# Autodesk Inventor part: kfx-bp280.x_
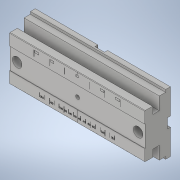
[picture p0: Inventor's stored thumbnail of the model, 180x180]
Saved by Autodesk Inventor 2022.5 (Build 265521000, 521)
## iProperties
Created: 2021-10
Part Number: kfx-bp280.x_
Material: 一般
Document SubType Name: Modeling
Designer: ImaoCorp
Density: 1 g/cm^3
Appearance: 既定
Sending System: SOLIDWORKS 2019-2019304
MC: AMD64
MC_MODEL: Intel64 Family 6 Model 60 Stepping 3, GenuineIntel
OS: Windows_NT
FRU: Parasolid Version 31.0, build 290,  9- 1-2019
FORMAT: text
GUISE: transmit
KEY: kfx-bp280
FILE: kfx-bp280.x_t
DATE: Thu Oct 14 10:00:54 2021
Author: ImaoCorp
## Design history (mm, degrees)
feature "Base1"
node "ソリッド1"
